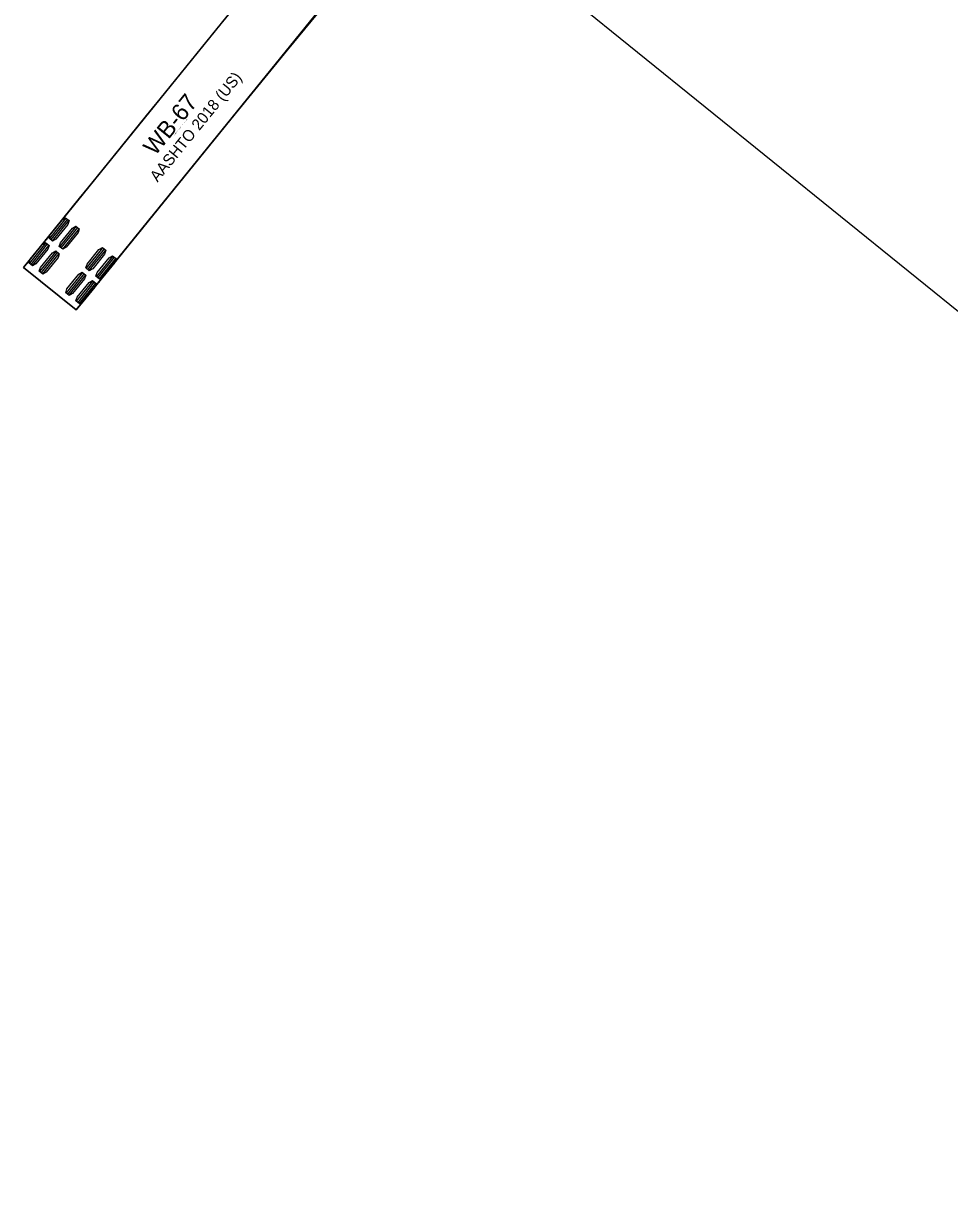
# Model space of a CAD drawing. Extents: x 2293233 to 2294507, y 892788 to 894229.
# Drawn here: x 2293428.6 to 2293544.7, y 892865.5 to 893014 of the extents above; entities that cross this region are included whole.
import ezdxf

# ---------------------------------------------------------------- set-up
doc = ezdxf.new("R2010")
doc.units = 0
doc.layers.add('COGO Default Curve', color=7, linetype='Continuous')
doc.layers.add('Prop Horizontal Alignment', color=7, linetype='Continuous')

msp = doc.modelspace()

# ---------------------------------------------------------------- linework, layer by layer
at = {"layer": 'COGO Default Curve'}
for p, q in [((2293461.9, 893024.59), (2293428.55, 892983.39)), ((2293435.16, 892978.05), (2293468.51, 893019.24)), ((2293433.86, 892989.58), (2293431.78, 892987.02)), ((2293434.04, 892989.44), (2293431.96, 892986.88)), ((2293434.22, 892989.3), (2293432.14, 892986.73)), ((2293435.14, 892988.55), (2293433.07, 892985.98)), ((2293435.32, 892988.4), (2293433.24, 892985.84)), ((2293435.5, 892988.26), (2293433.42, 892985.69)), ((2293431.34, 892986.48), (2293429.27, 892983.91)), ((2293431.52, 892986.33), (2293429.44, 892983.77)), ((2293431.7, 892986.19), (2293429.62, 892983.62)), ((2293432.62, 892985.44), (2293430.55, 892982.87)), ((2293438.47, 892985.85), (2293436.39, 892983.29)), ((2293438.65, 892985.71), (2293436.57, 892983.14)), ((2293438.83, 892985.56), (2293436.75, 892983)), ((2293432.8, 892985.29), (2293430.73, 892982.73)), ((2293432.98, 892985.15), (2293430.9, 892982.58)), ((2293439.75, 892984.81), (2293437.68, 892982.25)), ((2293439.93, 892984.67), (2293437.86, 892982.1)), ((2293440.11, 892984.53), (2293438.03, 892981.96)), ((2293428.55, 892983.39), (2293435.16, 892978.05)), ((2293435.95, 892982.74), (2293433.88, 892980.18)), ((2293436.13, 892982.6), (2293434.06, 892980.03)), ((2293436.31, 892982.45), (2293434.23, 892979.89)), ((2293437.24, 892981.7), (2293435.16, 892979.14)), ((2293437.41, 892981.56), (2293435.34, 892979)), ((2293437.59, 892981.42), (2293435.52, 892978.85))]:
    msp.add_line(p, q, dxfattribs=at)
for points in [[(2293429.41, 892984.45), (2293469.68, 893034.18), (2293477.94, 893044.22), (2293485.65, 893053.41), (2293490.41, 893058.99), (2293495.21, 893064.53), (2293500.06, 893070.03), (2293504.94, 893075.5), (2293509.87, 893080.93), (2293514.83, 893086.32), (2293519.84, 893091.67), (2293524.66, 893096.74), (2293530.22, 893102.5), (2293535.82, 893108.2), (2293541.47, 893113.86), (2293547.17, 893119.47)], [(2293545.7, 893104.49), (2293540.52, 893099.3), (2293535.15, 893093.83), (2293529.59, 893088.08), (2293523.84, 893082.04), (2293518.37, 893076.2), (2293512.72, 893070.08), (2293507.11, 893063.91), (2293501.56, 893057.69), (2293495.82, 893051.19), (2293490.13, 893044.65), (2293484.71, 893038.33), (2293479.32, 893031.97), (2293473.54, 893025.07), (2293467.58, 893017.89), (2293461.65, 893010.68), (2293455.12, 893002.67), (2293435.78, 892978.82), (2293435.35, 892978.31), (2293435.16, 892978.05), (2293428.55, 892983.39), (2293429.41, 892984.45)], [(2293431.38, 892986.89), (2293433.48, 892989.48), (2293435.58, 892992.07), (2293437.68, 892994.67), (2293439.78, 892997.26), (2293441.88, 892999.85), (2293443.98, 893002.44), (2293446.08, 893005.03), (2293448.18, 893007.62), (2293450.29, 893010.21), (2293452.4, 893012.79), (2293454.51, 893015.38)], [(2293437.99, 892981.54), (2293440.09, 892984.14), (2293442.19, 892986.73), (2293444.28, 892989.32), (2293446.38, 892991.91), (2293448.48, 892994.5), (2293450.58, 892997.08), (2293452.68, 892999.67), (2293454.78, 893002.25), (2293456.88, 893004.84), (2293458.98, 893007.42), (2293461.09, 893009.99), (2293463.2, 893012.57), (2293465.31, 893015.14)]]:
    msp.add_lwpolyline(points, dxfattribs=at)
for points in [[(2293433.81, 892989.62), (2293434.26, 892989.26), (2293434.1, 892988.79), (2293432.61, 892986.95), (2293432.18, 892986.7), (2293431.74, 892987.06), (2293431.9, 892987.52), (2293433.39, 892989.37)], [(2293435.1, 892988.58), (2293435.54, 892988.22), (2293435.39, 892987.75), (2293433.89, 892985.91), (2293433.47, 892985.66), (2293433.02, 892986.02), (2293433.18, 892986.48), (2293434.67, 892988.33)], [(2293431.3, 892986.51), (2293431.74, 892986.15), (2293431.59, 892985.68), (2293430.09, 892983.84), (2293429.67, 892983.59), (2293429.22, 892983.95), (2293429.38, 892984.41), (2293430.87, 892986.26)], [(2293432.58, 892985.47), (2293433.03, 892985.11), (2293432.87, 892984.65), (2293431.37, 892982.8), (2293430.95, 892982.55), (2293430.5, 892982.91), (2293430.66, 892983.38), (2293432.16, 892985.22)], [(2293438.43, 892985.89), (2293438.87, 892985.53), (2293438.71, 892985.06), (2293437.22, 892983.21), (2293436.79, 892982.96), (2293436.35, 892983.32), (2293436.51, 892983.79), (2293438, 892985.64)], [(2293439.71, 892984.85), (2293440.15, 892984.49), (2293440, 892984.02), (2293438.5, 892982.18), (2293438.08, 892981.92), (2293437.63, 892982.28), (2293437.79, 892982.75), (2293439.28, 892984.6)], [(2293435.91, 892982.78), (2293436.35, 892982.42), (2293436.2, 892981.95), (2293434.7, 892980.1), (2293434.28, 892979.85), (2293433.83, 892980.21), (2293433.99, 892980.68), (2293435.49, 892982.53)], [(2293437.19, 892981.74), (2293437.64, 892981.38), (2293437.48, 892980.91), (2293435.99, 892979.07), (2293435.56, 892978.82), (2293435.12, 892979.18), (2293435.27, 892979.64), (2293436.77, 892981.49)]]:
    msp.add_lwpolyline(points, close=True, dxfattribs=at)
for centre in [(2293431.38, 892986.89), (2293437.99, 892981.54)]:
    msp.add_circle(centre, 0.0417, dxfattribs=at)
at = {"layer": 'Prop Horizontal Alignment'}
msp.add_line((2293472.08, 893037.57), (2293684.67, 892865.5), dxfattribs=at)

# ---------------------------------------------------------------- texts
at = {"layer": 'COGO Default Curve'}
for s, height, p in [('AASHTO 2018 (US)', 1.4167, (2293445.36, 892994.02)), ('WB-67', 2.125, (2293445.05, 892997.3)), ('(c) 2022 Transoft Solutions, Inc. All rights reserved.', 0.085, (2293447.47, 892999.94))]:
    msp.add_text(s, height=height, rotation=51.0125, dxfattribs=at).set_placement(p)

doc.saveas('drawing.dxf')
